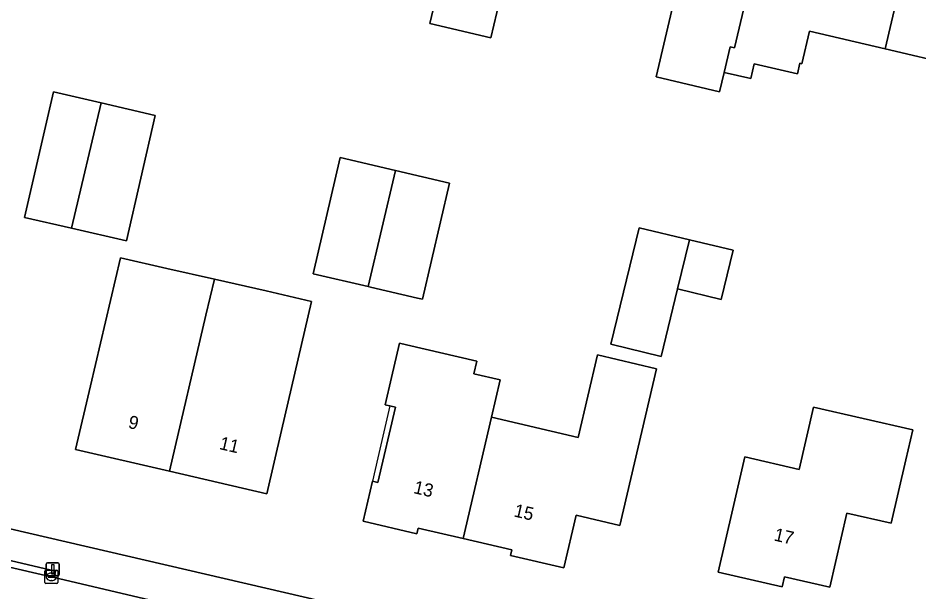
# Model space of a CAD drawing. Extents: x 162184 to 163154, y 385507 to 386516.
# Drawn here: x 162561.2 to 162630.3, y 385772.3 to 385816.4 of the extents above; entities that cross this region are included whole.
import ezdxf

# ---------------------------------------------------------------- set-up
doc = ezdxf.new("R2010")
doc.units = 0
for name, color, linetype in [('IMGEO_Erf', 7, 'Continuous'), ('IMGEO_Kolk', 7, 'Continuous'), ('IMGEO_Lichtmast', 7, 'Continuous'), ('IMGEO_Pand', 7, 'Continuous'), ('IMGEO_Pand_nummerreeks', 7, 'Continuous'), ('IMGEO_Pand_overbouw', 7, 'Continuous'), ('IMGEO_Rijbaan_lokaal_open', 7, 'Continuous'), ('IMGEO_Voetpad_open', 7, 'Continuous')]:
    doc.layers.add(name, color=color, linetype=linetype)

msp = doc.modelspace()

# ---------------------------------------------------------------- linework, layer by layer
at = {"layer": 'IMGEO_Erf'}
for points in [[(162598.605, 385819.73), (162597.457, 385814.841), (162592.778, 385815.939), (162593.156, 385817.554)], [(162633.135, 385812.73), (162627.689, 385814.008), (162621.902, 385815.367), (162621.313, 385812.858), (162621.156, 385812.895), (162620.964, 385812.077), (162617.65, 385812.855), (162617.383, 385811.714), (162615.344, 385812.192), (162614.997, 385810.714), (162610.122, 385811.858), (162611.606, 385818.183)], [(162493.7, 385792.713), (162500, 385791.251), (162664.68, 385753.025), (162666.341, 385752.639)]]:
    msp.add_lwpolyline(points, dxfattribs=at)
for points in [[(162569.513, 385799.274), (162565.316, 385800.238), (162561.709, 385801.067), (162563.92, 385810.694), (162567.567, 385809.856), (162571.724, 385808.901)], [(162594.295, 385803.694), (162592.21, 385794.793), (162591.83, 385794.882), (162588.227, 385795.726), (162588.055, 385795.766), (162583.825, 385796.756), (162585.913, 385805.668), (162590.141, 385804.672)], [(162612.681, 385799.362), (162616.034, 385798.572), (162615.117, 385794.788), (162611.769, 385795.598), (162610.515, 385790.42), (162606.667, 385791.352), (162608.826, 385800.27)], [(162572.613, 385797.155), (162576.264, 385796.335), (162580.218, 385795.448), (162583.711, 385794.635), (162581.414, 385784.738), (162580.283, 385779.867), (162572.812, 385781.606), (162565.623, 385783.28), (162566.762, 385788.149), (162569.062, 385797.981)], [(162598.174, 385788.615), (162597.504, 385785.756), (162604.158, 385784.208), (162605.627, 385790.523), (162610.148, 385789.471), (162607.353, 385777.457), (162603.998, 385778.237), (162603.058, 385774.198), (162598.96, 385775.151), (162599.062, 385775.586), (162595.324, 385776.456), (162591.896, 385777.253), (162591.793, 385776.811), (162587.665, 385777.771), (162588.381, 385780.849), (162588.8, 385780.751), (162590.143, 385786.527), (162589.364, 385786.708), (162589.849, 385788.793), (162590.463, 385791.432), (162590.998, 385791.308), (162596.376, 385790.057), (162596.15, 385789.086)], [(162629.804, 385784.777), (162629.278, 385782.492), (162628.156, 385777.619), (162624.749, 385778.404), (162623.441, 385772.721), (162619.969, 385773.521), (162619.788, 385772.735), (162614.888, 385773.863), (162616.01, 385778.736), (162616.924, 385782.709), (162621.095, 385781.748), (162622.195, 385786.529)]]:
    msp.add_lwpolyline(points, close=True, dxfattribs=at)
at = {"layer": 'IMGEO_Kolk'}
for p, q in [((162563.25, 385773.084), (162563.25, 385773.936)), ((162563.325, 385774.01), (162564.177, 385774.01)), ((162563.738, 385773.79), (162563.763, 385773.79)), ((162564.251, 385773.936), (162564.251, 385773.084)), ((162564.177, 385773.01), (162563.325, 385773.01)), ((162563.509, 385773.504), (162563.509, 385773.516)), ((162563.947, 385773.467), (162563.549, 385773.467)), ((162563.552, 385773.553), (162563.95, 385773.553)), ((162563.761, 385773.23), (162563.736, 385773.23)), ((162563.993, 385773.516), (162563.993, 385773.504))]:
    msp.add_line(p, q, dxfattribs=at)
for points in [[(162563.25, 385773.084), (162563.25, 385773.936)], [(162563.325, 385774.01), (162564.177, 385774.01)], [(162564.251, 385773.936), (162564.251, 385773.084)], [(162564.177, 385773.01), (162563.325, 385773.01)]]:
    msp.add_lwpolyline(points, dxfattribs=at)
for centre, radius, start, end in [((162563.327, 385773.934), 0.0765, 91.55205, 178.44795), ((162563.327, 385773.934), 0.0765, 91.55205, 178.44795), ((162564.175, 385773.934), 0.0765, 1.55205, 88.44795), ((162564.175, 385773.934), 0.0765, 1.55205, 88.44795), ((162563.327, 385773.086), 0.0765, 181.55205, 268.44795), ((162563.327, 385773.086), 0.0765, 181.55205, 268.44795), ((162563.549, 385773.513), 0.0403, 85.87752, 175.75265), ((162563.546, 385773.503), 0.0366, 178.93798, 274.71019), ((162563.95, 385773.51), 0.043, 264.86636, 352.45326), ((162563.954, 385773.515), 0.0386, 1.73085, 96.63898), ((162564.175, 385773.086), 0.0765, 271.55205, 358.44795), ((162564.175, 385773.086), 0.0765, 271.55205, 358.44795)]:
    msp.add_arc(centre, radius, start, end, dxfattribs=at)
for centre, major_axis, ratio, start_param, end_param in [((162563.737, 385773.51), (-0.387, 0.002), 0.722429, 4.712389, 7.853982), ((162563.762, 385773.51), (-0.39, 0.002), 0.717154, 1.570796, 4.712389)]:
    msp.add_ellipse(centre, major_axis=major_axis, ratio=ratio, start_param=start_param, end_param=end_param, dxfattribs=at)
at = {"layer": 'IMGEO_Lichtmast'}
for p, q in [((162563.371, 385773.682), (162563.371, 385774.482)), ((162563.371, 385774.482), (162563.371, 385773.682)), ((162563.471, 385774.582), (162564.261, 385774.582)), ((162564.261, 385774.582), (162563.471, 385774.582)), ((162564.361, 385774.482), (162564.361, 385773.682)), ((162564.361, 385773.682), (162564.361, 385774.482)), ((162564.261, 385773.582), (162563.471, 385773.582)), ((162563.471, 385773.582), (162564.261, 385773.582))]:
    msp.add_line(p, q, dxfattribs=at)
msp.add_lwpolyline([(162563.791, 385774.457), (162563.941, 385774.457), (162563.941, 385773.707), (162563.791, 385773.707), (162563.791, 385774.457)], dxfattribs=at)
for centre, start, end in [((162563.471, 385774.482), 90, 180), ((162563.471, 385774.482), 90, 180), ((162564.261, 385774.482), 0, 90), ((162564.261, 385774.482), 360, 90), ((162563.471, 385773.682), 180, 270), ((162563.471, 385773.682), 180, 270), ((162564.261, 385773.682), 270, 0), ((162564.261, 385773.682), 270, 0)]:
    msp.add_arc(centre, 0.1, start, end, dxfattribs=at)
at = {"layer": 'IMGEO_Pand'}
for points in [[(162607.694, 385829.233), (162600.389, 385830.947), (162599.501, 385827.165), (162599.157, 385827.245), (162598.464, 385824.291), (162598.804, 385824.212), (162598.644, 385823.53), (162594.768, 385824.44), (162593.156, 385817.554), (162592.778, 385815.939), (162597.457, 385814.841), (162598.605, 385819.73), (162601.255, 385819.108), (162601.589, 385820.534), (162605.443, 385819.629)], [(162613.329, 385820.385), (162613.488, 385821.063), (162613.824, 385820.984), (162614.496, 385823.846), (162614.158, 385823.926), (162615.001, 385827.518), (162607.694, 385829.233), (162605.443, 385819.629), (162611.606, 385818.183), (162610.122, 385811.858), (162614.997, 385810.714), (162615.344, 385812.192), (162615.803, 385814.151), (162616.135, 385814.073), (162617.865, 385821.44), (162617.702, 385821.478), (162617.23, 385819.47)], [(162630.025, 385823.952), (162622.434, 385825.734), (162621.239, 385820.642), (162620.961, 385819.458), (162617.752, 385820.212), (162618.031, 385821.401), (162617.865, 385821.44), (162616.135, 385814.073), (162615.803, 385814.151), (162615.344, 385812.192), (162617.383, 385811.714), (162617.65, 385812.855), (162620.964, 385812.077), (162621.156, 385812.895), (162621.313, 385812.858), (162621.902, 385815.367), (162627.689, 385814.008)], [(162637.005, 385819.56), (162637.617, 385822.17), (162630.025, 385823.952), (162627.689, 385814.008), (162633.135, 385812.73), (162632.544, 385810.213), (162638.06, 385808.918), (162638.545, 385810.98), (162639.516, 385815.111), (162636.146, 385815.902)], [(162567.567, 385809.856), (162563.92, 385810.694), (162561.709, 385801.067), (162565.316, 385800.238)], [(162565.316, 385800.238), (162569.513, 385799.274), (162571.724, 385808.901), (162567.567, 385809.856)], [(162590.141, 385804.672), (162585.913, 385805.668), (162583.825, 385796.756), (162588.055, 385795.766)], [(162588.227, 385795.726), (162591.83, 385794.882), (162592.21, 385794.793), (162594.295, 385803.694), (162590.141, 385804.672), (162588.055, 385795.766)], [(162612.681, 385799.362), (162608.826, 385800.27), (162606.667, 385791.352), (162610.515, 385790.42), (162611.769, 385795.598)], [(162611.769, 385795.598), (162615.117, 385794.788), (162616.034, 385798.572), (162612.681, 385799.362)], [(162575.615, 385793.566), (162576.264, 385796.335), (162572.613, 385797.155), (162569.062, 385797.981), (162566.762, 385788.149), (162565.623, 385783.28), (162572.812, 385781.606)], [(162583.711, 385794.635), (162580.218, 385795.448), (162576.264, 385796.335), (162575.615, 385793.566), (162572.812, 385781.606), (162580.283, 385779.867), (162581.414, 385784.738)], [(162598.174, 385788.615), (162596.15, 385789.086), (162596.376, 385790.057), (162590.998, 385791.308), (162590.463, 385791.432), (162589.849, 385788.793), (162589.364, 385786.708), (162590.143, 385786.527), (162588.8, 385780.751), (162588.381, 385780.849), (162587.665, 385777.771), (162591.793, 385776.811), (162591.896, 385777.253), (162595.324, 385776.456), (162597.504, 385785.756)], [(162610.148, 385789.471), (162605.627, 385790.523), (162604.158, 385784.208), (162597.504, 385785.756), (162595.324, 385776.456), (162599.062, 385775.586), (162598.96, 385775.151), (162603.058, 385774.198), (162603.998, 385778.237), (162607.353, 385777.457)], [(162622.195, 385786.529), (162621.095, 385781.748), (162616.924, 385782.709), (162616.01, 385778.736), (162614.888, 385773.863), (162619.788, 385772.735), (162619.969, 385773.521), (162623.441, 385772.721), (162624.749, 385778.404), (162628.156, 385777.619), (162629.278, 385782.492), (162629.804, 385784.777)]]:
    msp.add_lwpolyline(points, close=True, dxfattribs=at)
at = {"layer": 'IMGEO_Pand_overbouw'}
msp.add_lwpolyline([(162588.798, 385782.642), (162588.381, 385780.849), (162588.8, 385780.751), (162590.143, 385786.527), (162589.724, 385786.624)], close=True, dxfattribs=at)
at = {"layer": 'IMGEO_Rijbaan_lokaal_open'}
msp.add_lwpolyline([(162640.182, 385755.714), (162624.181, 385759.421), (162620.419, 385760.293), (162604.314, 385764.025), (162600.787, 385764.842), (162585.277, 385768.474), (162578.556, 385770.031), (162563.973, 385773.461), (162555.782, 385775.359)], dxfattribs=at)
at = {"layer": 'IMGEO_Voetpad_open'}
for points in [[(162666.341, 385752.639), (162664.68, 385753.025), (162500, 385791.251)], [(162555.9, 385775.857), (162564.089, 385773.951), (162563.973, 385773.461), (162578.556, 385770.031), (162578.669, 385770.507), (162585.388, 385768.943), (162585.277, 385768.474), (162600.787, 385764.842), (162600.896, 385765.305), (162604.423, 385764.488), (162604.314, 385764.025), (162620.419, 385760.293), (162620.528, 385760.756), (162624.291, 385759.888), (162624.181, 385759.421), (162640.182, 385755.714)]]:
    msp.add_lwpolyline(points, dxfattribs=at)
msp.add_lwpolyline([(162563.973, 385773.461), (162564.089, 385773.951), (162555.9, 385775.857), (162555.782, 385775.359)], close=True, dxfattribs=at)

# ---------------------------------------------------------------- texts
at = {"layer": 'IMGEO_Pand_nummerreeks'}
for s, rotation, p in [('9', 346.89646, (162569.592, 385784.944)), ('11', 346.89646, (162576.584, 385783.316)), ('13', 346.9044, (162591.47, 385779.939)), ('15', 346.90218, (162599.165, 385778.15)), ('17', 347.02467, (162619.104, 385776.306))]:
    msp.add_text(s, height=1, rotation=rotation, dxfattribs=at).set_placement(p)

doc.saveas('drawing.dxf')
